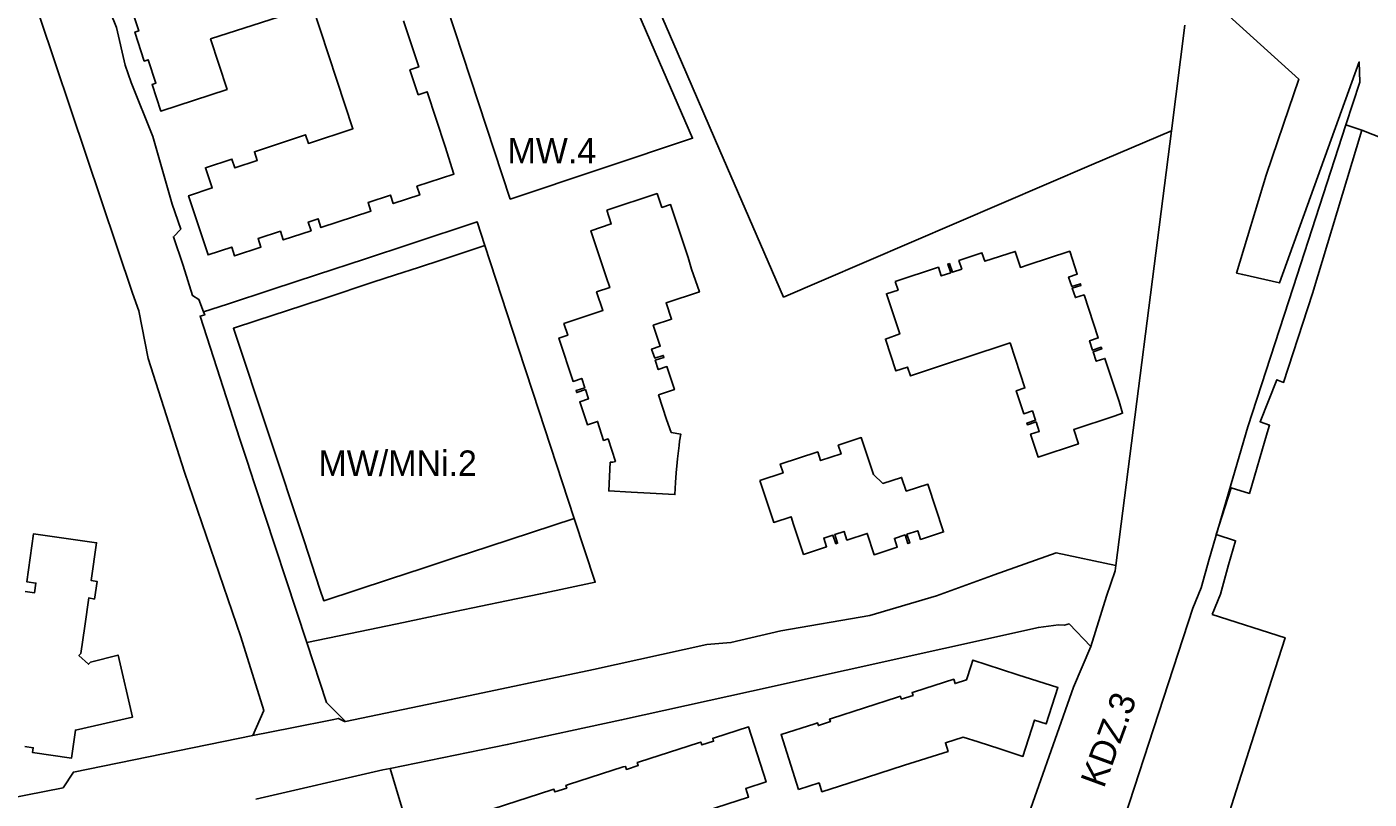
# Model space of a CAD drawing. Extents: x 7416797 to 7419013, y 5549660 to 5551534.
# Drawn here: x 7417614 to 7417878.3, y 5550472.8 to 5550624.8 of the extents above; entities that cross this region are included whole.
import ezdxf

# ---------------------------------------------------------------- set-up
doc = ezdxf.new("R2010")
doc.units = 0
for name, color, linetype in [('LIN_Linia Zabudowy Nieprzekraczalna', 7, 'Continuous'), ('LIN_Linia Zabudowy Obowiązujaca', 7, 'Continuous'), ('LIN_linie_rozgraniczajace', 7, 'Continuous'), ('TXT_Oznaczenia_przeznaczen', 7, 'Continuous')]:
    doc.layers.add(name, color=color, linetype=linetype)

msp = doc.modelspace()

# ---------------------------------------------------------------- linework, layer by layer
at = {"layer": 'LIN_Linia Zabudowy Nieprzekraczalna'}
msp.add_lwpolyline([(7417688.86, 5550652.64), (7417709.16, 5550590.9), (7417745.08, 5550602.9), (7417739.25, 5550616.34), (7417718.08, 5550665.17)], close=True, dxfattribs=at)
for points in [[(7417876.89, 5550604.46), (7417867.16, 5550572.32), (7417861.47, 5550554.82), (7417860.12, 5550555.35), (7417856.84, 5550547.09), (7417858.73, 5550546.38), (7417858.25, 5550544.91), (7417854.76, 5550532.96), (7417851.18, 5550534.1), (7417848.23, 5550524.89), (7417852.04, 5550523.66), (7417850.66, 5550518.95), (7417849.07, 5550513.13), (7417847.44, 5550509.14)], [(7417704.18, 5550581.76), (7417695.69, 5550578.97), (7417691.12, 5550577.46), (7417686.6, 5550575.98), (7417682.14, 5550574.53), (7417672.74, 5550571.43), (7417668.33, 5550569.98), (7417659.24, 5550566.99), (7417654.66, 5550565.48), (7417668.57, 5550523.63), (7417671.68, 5550514.11), (7417672.43, 5550511.84), (7417685.38, 5550516.09), (7417692.05, 5550518.28), (7417698.32, 5550520.34), (7417704.95, 5550522.52), (7417721.79, 5550528.05)], [(7417847.44, 5550509.14), (7417861.79, 5550504.58), (7417859.19, 5550496.4), (7417851.71, 5550472.97), (7417844.38, 5550449.89), (7417842.25, 5550442.95), (7417829.22, 5550447), (7417823.43, 5550448.8), (7417802.63, 5550384.88), (7417799.31, 5550374.64), (7417780.6, 5550316.7), (7417780.05, 5550314.74), (7417800.75, 5550309.44), (7417809.6, 5550305.82), (7417801.84, 5550282), (7417809.66, 5550279.48)]]:
    msp.add_lwpolyline(points, dxfattribs=at)
at = {"layer": 'LIN_Linia Zabudowy Obowiązujaca'}
for points in [[(7417634.32, 5550629.22), (7417636.01, 5550624.02), (7417635.24, 5550623.77), (7417637.1, 5550618.08), (7417637.86, 5550618.33), (7417639.38, 5550613.7), (7417638.62, 5550613.46), (7417640.34, 5550608.23), (7417653.41, 5550612.5), (7417650.16, 5550622.44), (7417670.21, 5550628.87), (7417678.18, 5550604.75), (7417669.44, 5550601.86), (7417668.88, 5550603.57), (7417658.78, 5550600.24), (7417659.35, 5550598.51), (7417654.93, 5550597.06), (7417654.36, 5550598.79), (7417649.15, 5550597.07), (7417650.48, 5550593.1), (7417645.82, 5550591.56), (7417649.67, 5550579.91), (7417654.31, 5550581.45), (7417654.87, 5550579.74), (7417660.06, 5550581.44), (7417659.5, 5550583.14), (7417663.92, 5550584.59), (7417664.48, 5550582.88), (7417669.95, 5550584.67), (7417669.38, 5550586.39), (7417671.33, 5550587.03), (7417671.9, 5550585.31), (7417681.73, 5550588.55), (7417681.16, 5550590.26), (7417685.58, 5550591.71), (7417686.14, 5550590.01), (7417691.35, 5550591.72), (7417690.78, 5550593.43), (7417698.07, 5550595.84), (7417696.34, 5550601.24), (7417692.78, 5550612.03), (7417691.04, 5550611.45), (7417689.43, 5550616.35), (7417691.15, 5550616.91), (7417688.17, 5550625.98)], [(7417613.56, 5550483.14), (7417615.24, 5550482.91), (7417615.11, 5550481.97), (7417622.77, 5550480.89), (7417623.54, 5550486.38), (7417634.77, 5550488.93), (7417631.95, 5550501.16), (7417626.48, 5550499.76), (7417626.09, 5550499.34), (7417624.23, 5550501.05), (7417624.62, 5550501.47), (7417625.37, 5550506.85), (7417626.15, 5550512.4), (7417627.29, 5550512.17), (7417627.81, 5550515.67), (7417626.65, 5550515.81), (7417627.71, 5550523.28), (7417615.29, 5550525.03), (7417613.94, 5550515.58), (7417615.77, 5550515.34), (7417615.51, 5550513.42), (7417613.65, 5550513.7)], [(7417747.55, 5550470.45), (7417756.11, 5550473.19), (7417755.56, 5550474.9), (7417759.57, 5550476.18), (7417756.11, 5550487.02), (7417749.43, 5550484.89), (7417749.04, 5550484.77), (7417749.22, 5550484.2), (7417746.88, 5550483.46), (7417746.7, 5550484.03), (7417746.28, 5550483.89), (7417734.63, 5550480.15), (7417734.18, 5550479.98), (7417734.37, 5550479.4), (7417732.04, 5550478.66), (7417731.85, 5550479.24), (7417731.44, 5550479.13), (7417720.66, 5550475.67), (7417720.13, 5550475.5), (7417720.3, 5550474.97), (7417717.96, 5550474.23), (7417717.79, 5550474.76), (7417717.39, 5550474.63), (7417705.8, 5550470.91)]]:
    msp.add_lwpolyline(points, dxfattribs=at)
for points in [[(7417728.18, 5550588.71), (7417729.08, 5550586.01), (7417725.07, 5550584.69), (7417728.07, 5550575.62), (7417728.78, 5550573.48), (7417726.18, 5550572.63), (7417727.41, 5550568.96), (7417719.73, 5550566.41), (7417720.49, 5550564.12), (7417718.77, 5550563.56), (7417721.56, 5550555.02), (7417723.27, 5550555.61), (7417723.85, 5550553.78), (7417722.15, 5550553.23), (7417722.28, 5550552.81), (7417723.99, 5550553.4), (7417724.57, 5550551.57), (7417722.87, 5550551.02), (7417724.37, 5550546.48), (7417726.36, 5550547.16), (7417727.57, 5550543.42), (7417728.44, 5550543.69), (7417729.89, 5550539.26), (7417729.35, 5550539.1), (7417728.87, 5550539.12), (7417728.58, 5550533.47), (7417732.98, 5550533.23), (7417735.49, 5550533.07), (7417741.59, 5550532.76), (7417741.71, 5550535.11), (7417741.84, 5550537.04), (7417742.04, 5550539.03), (7417742.11, 5550539.81), (7417742.43, 5550542.38), (7417742.53, 5550543.28), (7417742.75, 5550544.67), (7417740.89, 5550544.98), (7417739.97, 5550547.52), (7417738.39, 5550552.37), (7417741.52, 5550553.41), (7417740.03, 5550557.94), (7417738.33, 5550557.35), (7417737.74, 5550559.18), (7417739.44, 5550559.74), (7417739.31, 5550560.15), (7417737.62, 5550559.61), (7417737.01, 5550561.38), (7417738.72, 5550561.94), (7417737.35, 5550566.08), (7417740.94, 5550567.25), (7417739.88, 5550570.48), (7417746.42, 5550572.63), (7417744.9, 5550577.14), (7417744.33, 5550578.98), (7417744.2, 5550579.38), (7417743.61, 5550581.18), (7417740.76, 5550589.84), (7417739.04, 5550589.26), (7417738.1, 5550591.99)], [(7417785.01, 5550574.71), (7417785.57, 5550573.01), (7417783.27, 5550572.27), (7417785.88, 5550564.37), (7417783.06, 5550563.34), (7417785.11, 5550557.09), (7417787.38, 5550557.85), (7417787.98, 5550556.11), (7417796.47, 5550558.95), (7417798.7, 5550559.69), (7417807.61, 5550562.6), (7417809.6, 5550556.6), (7417810.54, 5550553.75), (7417808.83, 5550553.17), (7417810.31, 5550548.67), (7417812.02, 5550549.23), (7417812.63, 5550547.37), (7417810.92, 5550546.81), (7417811.03, 5550546.48), (7417812.74, 5550547.04), (7417813.35, 5550545.19), (7417811.64, 5550544.63), (7417813.12, 5550540.12), (7417821.07, 5550542.72), (7417820.15, 5550545.57), (7417828.13, 5550548.21), (7417829.77, 5550548.74), (7417829.09, 5550551.04), (7417826.29, 5550559.56), (7417824.58, 5550558.98), (7417823.97, 5550560.83), (7417825.68, 5550561.41), (7417825.57, 5550561.74), (7417823.86, 5550561.17), (7417823.26, 5550563.01), (7417824.97, 5550563.57), (7417822.18, 5550572.06), (7417820.47, 5550571.51), (7417819.87, 5550573.36), (7417821.58, 5550573.91), (7417821.47, 5550574.25), (7417819.76, 5550573.7), (7417819.15, 5550575.57), (7417820.85, 5550576.14), (7417819.37, 5550580.65), (7417811.19, 5550577.97), (7417809.66, 5550577.47), (7417808.63, 5550580.6), (7417802.65, 5550578.66), (7417802.08, 5550580.35), (7417797.53, 5550578.82), (7417798.1, 5550577.13), (7417796.25, 5550576.51), (7417795.68, 5550578.21), (7417795.34, 5550578.1), (7417795.92, 5550576.4), (7417794.07, 5550575.79), (7417793.51, 5550577.5)], [(7417758.35, 5550535.5), (7417761.07, 5550527.26), (7417764.49, 5550528.39), (7417764.99, 5550526.87), (7417766.93, 5550520.97), (7417771.48, 5550522.48), (7417770.91, 5550524.18), (7417772.73, 5550524.78), (7417773.3, 5550523.06), (7417773.65, 5550523.17), (7417773.08, 5550524.89), (7417774.92, 5550525.49), (7417775.47, 5550523.78), (7417779.47, 5550525.1), (7417780.84, 5550520.92), (7417785.38, 5550522.42), (7417784.84, 5550524.12), (7417786.93, 5550524.81), (7417787.5, 5550523.11), (7417787.84, 5550523.22), (7417787.3, 5550524.93), (7417789.44, 5550525.63), (7417790, 5550523.92), (7417794.51, 5550525.4), (7417791.43, 5550534.78), (7417787.17, 5550533.44), (7417786.26, 5550536.14), (7417782.56, 5550534.95), (7417780.7, 5550536.73), (7417778.29, 5550543.96), (7417773.77, 5550542.47), (7417774.33, 5550540.76), (7417770.3, 5550539.45), (7417769.74, 5550541.15), (7417762.36, 5550538.75), (7417762.91, 5550537)], [(7417765.97, 5550474.69), (7417769.99, 5550475.98), (7417770.54, 5550474.27), (7417779.34, 5550477.09), (7417786.82, 5550479.48), (7417795.42, 5550482.21), (7417794.87, 5550483.91), (7417798.37, 5550485.03), (7417801.3, 5550484.09), (7417805.61, 5550482.69), (7417810.14, 5550481.22), (7417812.44, 5550488.36), (7417814.74, 5550487.62), (7417817.04, 5550494.75), (7417809.17, 5550497.29), (7417805.95, 5550498.33), (7417800.27, 5550500.18), (7417799.93, 5550499.12), (7417799.01, 5550496.26), (7417796.79, 5550495.55), (7417796.51, 5550496.41), (7417788.76, 5550493.92), (7417788.33, 5550493.78), (7417788.51, 5550493.23), (7417786.17, 5550492.48), (7417786, 5550493.04), (7417785.42, 5550492.85), (7417772.46, 5550488.7), (7417772.06, 5550488.57), (7417772.23, 5550488.05), (7417769.87, 5550487.29), (7417769.7, 5550487.81), (7417769.14, 5550487.63), (7417762.52, 5550485.51)]]:
    msp.add_lwpolyline(points, close=True, dxfattribs=at)
at = {"layer": 'LIN_linie_rozgraniczajace'}
for points in [[(7417583.18, 5550784.07), (7417636.6, 5550769.97), (7417648.21, 5550734.66), (7417661.07, 5550695.58), (7417675.38, 5550652.06), (7417683.92, 5550654.87), (7417720.17, 5550670.42), (7417723.95, 5550661.71), (7417742.92, 5550617.93), (7417750.48, 5550600.49), (7417755.45, 5550589.02), (7417763, 5550571.61), (7417770.45, 5550574.8), (7417823.65, 5550597.62), (7417839.38, 5550604.37)], [(7417658.47, 5550485.31), (7417660.63, 5550490.24), (7417656.11, 5550504.73), (7417645.04, 5550537.13), (7417637.84, 5550559.52), (7417636.02, 5550568.92), (7417634.8, 5550572.36), (7417607.34, 5550653.96), (7417597.31, 5550683.99), (7417596.78, 5550691.48), (7417584.23, 5550730.83)], [(7417648.78, 5550568.69), (7417647.81, 5550571.16), (7417646.62, 5550571.91), (7417644.73, 5550577.82), (7417642.84, 5550583.51), (7417644.28, 5550585), (7417642.56, 5550589.92), (7417638.76, 5550603.21), (7417634.53, 5550613.86), (7417633.32, 5550617.27), (7417631.62, 5550624.71), (7417625.94, 5550638.85)], [(7417843.12, 5550633.86), (7417861.05, 5550617.59), (7417864.45, 5550614.51), (7417861.43, 5550605.65), (7417858.03, 5550595.64), (7417852.21, 5550576.33), (7417853.44, 5550576.05), (7417860.65, 5550574.42), (7417876.38, 5550617.91), (7417876.47, 5550613.94), (7417873.74, 5550605.53)], [(7417842.01, 5550625.11), (7417839.38, 5550604.37)], [(7417873.74, 5550605.53), (7417863.34, 5550573.52), (7417854.43, 5550546.09), (7417846.81, 5550520.04), (7417845.27, 5550514.42), (7417843.62, 5550510.36), (7417824.36, 5550451.41), (7417823.69, 5550449.9), (7417823.43, 5550448.8), (7417802.63, 5550384.88), (7417799.31, 5550374.64), (7417780.6, 5550316.7), (7417780.05, 5550314.74), (7417779.59, 5550313.09), (7417768.36, 5550278.62), (7417773.52, 5550271.33)], [(7417839.38, 5550604.37), (7417828.42, 5550518.77)], [(7418092.7, 5550432.42), (7418071.51, 5550446.22), (7418057.57, 5550452.93), (7418047.73, 5550458.5), (7418040.72, 5550445.49), (7417999.52, 5550471.94), (7418014.05, 5550489.79), (7417968.97, 5550532.54), (7417954.56, 5550547.11), (7417895.48, 5550596.2), (7417893.88, 5550597.78), (7417876.89, 5550604.46), (7417876.86, 5550604.47), (7417873.74, 5550605.53)], [(7417648.78, 5550568.69), (7417653.49, 5550570.23), (7417662.24, 5550573.11), (7417671.22, 5550576.06), (7417680.47, 5550579.1), (7417689.59, 5550582.11), (7417702.66, 5550586.4), (7417704.18, 5550581.76), (7417710.76, 5550561.7), (7417713.64, 5550552.9), (7417721.79, 5550528.05), (7417725.9, 5550515.5), (7417715.11, 5550513.24), (7417708.46, 5550511.84), (7417698.32, 5550509.72), (7417688.17, 5550507.6), (7417681.53, 5550506.21), (7417669.08, 5550503.6)], [(7417669.08, 5550503.6), (7417658.8, 5550534.87), (7417657.28, 5550539.49), (7417655.91, 5550543.66), (7417648.1, 5550567.87), (7417649.01, 5550568.12), (7417648.78, 5550568.69)], [(7417676.74, 5550488.1), (7417697.54, 5550492.39), (7417725.57, 5550498.33), (7417747.91, 5550503.24), (7417752.62, 5550503.6), (7417762.48, 5550505.93), (7417779.98, 5550508.93), (7417793.12, 5550512.79), (7417803.96, 5550516.73), (7417804.51, 5550516.92), (7417816.66, 5550521.3), (7417828.42, 5550518.77)], [(7417828.42, 5550518.77), (7417828.31, 5550517.74), (7417826.59, 5550512.72), (7417823.49, 5550502.87)], [(7417823.49, 5550502.87), (7417819.28, 5550507.28), (7417818.32, 5550507.07), (7417817.13, 5550507.13), (7417813.21, 5550506.61), (7417756.71, 5550494.07), (7417731.09, 5550488.41), (7417708.6, 5550483.54), (7417685.5, 5550478.84)], [(7417676.74, 5550488.1), (7417672.99, 5550491.84), (7417669.08, 5550503.6)], [(7417771.39, 5550350.09), (7417771.85, 5550351.92), (7417774.55, 5550359.75), (7417782.3, 5550382.33), (7417786.12, 5550393.5), (7417786.33, 5550394.06), (7417789.82, 5550403.83), (7417795.58, 5550420.74), (7417797.58, 5550426.56), (7417807.67, 5550455.91), (7417807.81, 5550459.25), (7417809.26, 5550464.12), (7417820.13, 5550494.86), (7417823.49, 5550502.87)], [(7417658.47, 5550485.31), (7417666.16, 5550486.86), (7417674.07, 5550488.43), (7417675.32, 5550488.68), (7417676.56, 5550488.06), (7417676.74, 5550488.1)], [(7417509.99, 5550446.76), (7417537.56, 5550453.2), (7417540.46, 5550454.02), (7417578.72, 5550464.83), (7417580.92, 5550467.15), (7417621.12, 5550475.03), (7417623.13, 5550478.14), (7417658.47, 5550485.31)], [(7417685.5, 5550478.84), (7417684.07, 5550478.54), (7417659.07, 5550472.8)], [(7417685.5, 5550478.84), (7417693.58, 5550451.86), (7417719.23, 5550372.07), (7417722.66, 5550366.97), (7417771.39, 5550350.09)]]:
    msp.add_lwpolyline(points, dxfattribs=at)

# ---------------------------------------------------------------- texts
at = {"layer": 'TXT_Oznaczenia_przeznaczen'}
for s, p in [('MW.4', (7417708.64, 5550597.95)), ('MW/MNi.2', (7417671.4, 5550536.43))]:
    msp.add_text(s, height=5, dxfattribs=at).set_placement(p)
msp.add_text('KDZ.3', height=5, rotation=69.8311, dxfattribs=at).set_placement((7417826.07, 5550474.78))

doc.saveas('drawing.dxf')
